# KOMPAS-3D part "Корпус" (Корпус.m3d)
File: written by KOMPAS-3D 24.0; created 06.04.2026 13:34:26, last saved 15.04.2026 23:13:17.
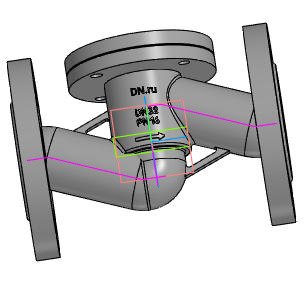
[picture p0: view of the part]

Document properties: Автор: R2D2; Полное имя файла: E:\Работа\Зайцев\VSO3131M-F-S Клапан запорный DN.ru Ду15-100 Ру16\DN32\исходные материалы\Корпус.m3d

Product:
- Body: Труба / Нестандартная труба / L = 89.9 мм  | qty 1
    Материал: Нестандартная труба (density 7856 kg/m3)
    Масса: 6.880971
    Раздел спецификации: Детали
    Примечание: 0,98 кг
    additional columns: Pipeline; 0.042; 0; 0; 0.002; 0.08987; true; 0.04
- Body: Труба / Нестандартная труба / L = 111.7 мм  | qty 1
    Материал: Нестандартная труба (density 7856 kg/m3)
    Масса: 6.880971
    Раздел спецификации: Детали
    Примечание: 1,22 кг
    additional columns: Pipeline; 0.042; 0; 0; 0.002; 0.11172; true; 0.04
- Body: Тело 4  | qty 1
    Материал: Нестандартная труба (density 7856 kg/m3)
    Масса: 6.880971
- Body: Тело 5  | qty 1
    Материал: Нестандартная труба (density 7856 kg/m3)
    Масса: 6.880971
- Body: Тело 8  | qty 1
    Материал: Нестандартная труба (density 7856 kg/m3)
    Масса: 6.880971
- Body: Тело 9  | qty 1
    Материал: Нестандартная труба (density 7856 kg/m3)
    Масса: 6.880971
- Part/product: Корпус
    Масса: 6.9

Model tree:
1. Труба
2. Труба:1  (labels: {F703FF30-5BE6-4673-A7F1-8EDA1BE1E2D1}; SHAPEOBJECT3D_ATTR_BUTT; SHAPEOBJECT3D_ATTR_VALID; SHAPEOBJECT3D_ATTR_BUTT_AREA)
     PIPE_R = 7
3. Труба:2  (labels: {F703FF30-5BE6-4673-A7F1-8EDA1BE1E2D1}; SHAPEOBJECT3D_ATTR_BUTT; SHAPEOBJECT3D_ATTR_VALID; SHAPEOBJECT3D_ATTR_BUTT_AREA)
     PIPE_R = 7
4. Колонна
5. Элемент выдавливания:1
     Смещение 1 = -1; Смещение 2 = -5
6. Скругление:17  (with: Ребро.Элемент выдавливания:1)
     Радиус = 1
7. Скругление:18  (with: Ребро.Элемент выдавливания:1)
8. Скругление:24  (with: Ребро.Элемент выдавливания:1)
     Радиус = 1.5
9. Элемент выдавливания:2
     Расстояние 1 = 6
10. Скругление:19  (with: Ребро.Элемент выдавливания:2)
     Радиус = 2
11. Эскиз:4  (with: Грань.Элемент выдавливания:1)
12. Элемент выдавливания:3
     Расстояние 1 = -6.5
13. Скругление:21  (with: Ребро.Элемент выдавливания:3)
14. ОТЛИВКА
15. Скругление:6  (with: Грань.Элемент выдавливания:1)
     Радиус = 2
16. Элемент выдавливания:6  (with: Грань.Элемент выдавливания:1)
     Смещение 1 = 4
17. ЛЕЙБЛ
18. Элемент выдавливания:7  (with: Грань.Элемент выдавливания:1)
     Расстояние 1 = 26.9987; Смещение 1 = 1
19. Фланец верх  (with: Ребро.Элемент выдавливания:3)  (labels: Клапан запорный DN.ru Ду32 Ру16)
20. Элемент вращения:2
     Угол 1 = 360
21. Эскиз:12  (with: Грань.Элемент вращения:2)
22. Элемент выдавливания:9  (with: Грань.Элемент вращения:2)
     Расстояние 2 = 20
23. Массив по концентрической сетке:1  (with: Элемент выдавливания:9, Эскиз:12, Грань.Элемент вращения:2)  (4 pattern instances)
     Шаг 2 = 360
24. Фланец
25. Элемент вращения:1
     Угол 1 = 360
26. отвертие во фланце  (with: Грань.Элемент вращения:1)
27. Элемент выдавливания:8
28. Массив по концентрической сетке:2  (with: Элемент выдавливания:8, Эскиз:10, Грань.Элемент вращения:1)  (4 pattern instances)
     Шаг 2 = 360
29. Зеркальный массив:1
30. Экземпляр ( 1 )
31. Экземпляр ( 2 )  (with: Элемент вращения:1, Массив по концентрической сетке:2, Экземпляр ( 1 ), Элемент выдавливания:8)
32. Экземпляр ( 3 )  (with: Элемент выдавливания:8)
33. Экземпляр ( 4 )  (with: Элемент выдавливания:8)
34. Скругление:25  (with: Ребро.Элемент вращения:2)
     Радиус = 2

Expressions: DS/2+3; D1/2; DN/2; DS-v977*4; LL/2; D1-v1234*2; D/2-24
Referenced files in C:\Program Files\ASCON\KOMPAS-3D v24\Libs\Pipeline\: StylesTemplate.a3d, TemplateHPH, InsulationStylesTemplate.a3d, Insulation
Referenced files in C:\Program Files\ASCON\KOMPAS-3D v24\Templates\: Констр. чертеж А3 гориз. перв. лист.cdt
Referenced files in E:\Работа\Зайцев\VSO3131M-F-S Клапан запорный DN.ru Ду15-100 Ру40\DN20\исходные материалы\: 
Referenced files in E:\Работа\Зайцев\VSO3131M-F-S Клапан запорный DN.ru Ду15-100 Ру16\DN32\исходные материалы\: VSO3131M-F-S Клапан запорный DN.ru Ду32 Ру16.a3d
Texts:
  Отводы ГОСТ 17375-2001
  Констр. чертеж А3 гориз. перв. лист.cdt
  GOST 26.020 Pr3
  var3D
  GOST 2.304 type A
  смещение колонны вниз
  LL-10
  DN+10
  Труба / Нестандартная труба / L = %s мм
